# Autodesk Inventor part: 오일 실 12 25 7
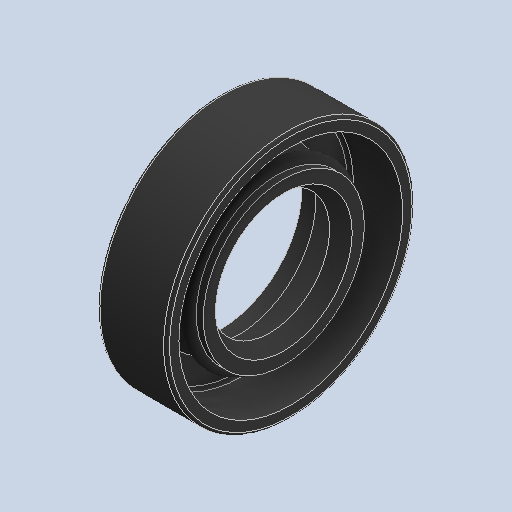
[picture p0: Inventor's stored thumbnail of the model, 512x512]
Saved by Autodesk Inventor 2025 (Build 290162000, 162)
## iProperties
Created: 2026-07
Part Number: 오일 실 12 25 7
Material: 고무
Description: 오일-실
Document SubType Name: Modeling
Designer: KDI
Density: 0.93 g/cm^3
Appearance: 기본값
Author: jhkim
Sending System: Autodesk Inventor 2027
Preprocessor: ST-DEVELOPER v20.1
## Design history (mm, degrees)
feature "Solid1"
node "솔리드1"
